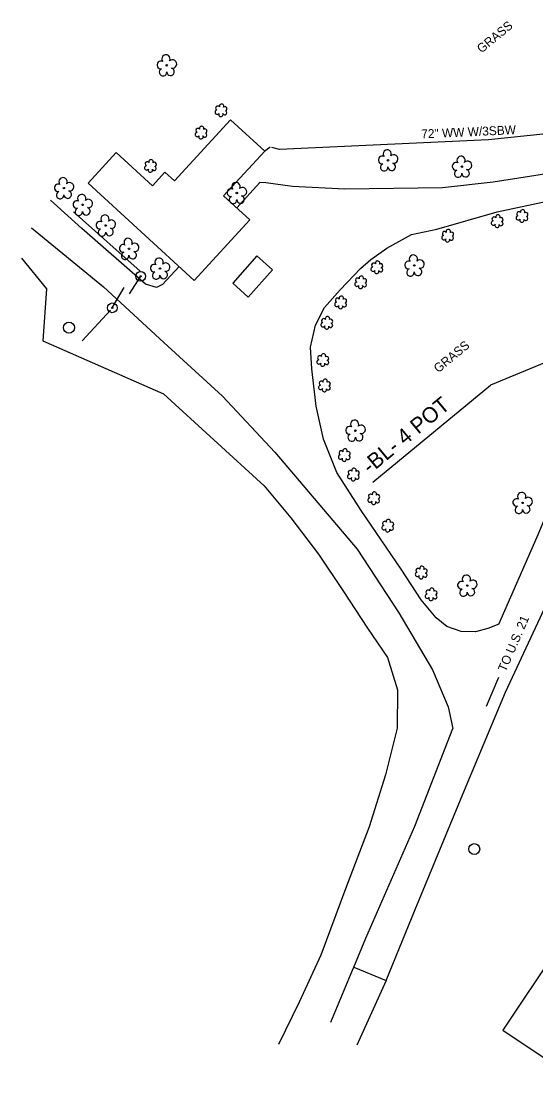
# Model space of a CAD drawing. Extents: x 1435573 to 1437263, y 981340 to 982884.
# Drawn here: x 1435573.4 to 1435804.6, y 981403.5 to 981887.2 of the extents above; entities that cross this region are included whole.
import ezdxf

# ---------------------------------------------------------------- set-up
doc = ezdxf.new("R2010")
doc.units = 0
for name, color, linetype in [('Exist Building', 7, 'Continuous'), ('Exist Horizontal Baseline Alignment Station Label', 7, 'Continuous'), ('Exist Other Culture Fence Line', 7, 'Continuous'), ('Exist Other Culture Fence Line Text', 7, 'Continuous'), ('Exist Other Culture Gate', 7, 'Continuous'), ('Exist Other Culture Located Object CELL', 7, 'Continuous'), ('Exist Roads EOP', 7, 'Continuous'), ('Exist Roads EOP Leader', 7, 'Continuous'), ('Exist Roads EOP Other', 7, 'Continuous'), ('Exist Roads EOP Text', 7, 'Continuous'), ('Exist Roads Soil', 7, 'Continuous'), ('Exist Utilities Other Pole CELL', 7, 'Continuous'), ('Exist Vegetation Shrub CELL', 7, 'Continuous'), ('Exist Vegetation Shrub Text', 7, 'Continuous'), ('Exist Vegetation Tree CELL', 7, 'Continuous'), ('Exist Vegetation Woods Line', 7, 'Continuous')]:
    doc.layers.add(name, color=color, linetype=linetype)

msp = doc.modelspace()

# ---------------------------------------------------------------- linework, layer by layer
at = {"layer": 'Exist Building'}
for points in [[(1435651.11, 981770.64), (1435603.35, 981814.47), (1435615.96, 981828.21), (1435632.3, 981813.22), (1435637.97, 981819.4), (1435642.23, 981815.49), (1435667.44, 981842.95), (1435682.81, 981828.84), (1435664.34, 981808.71), (1435676.12, 981797.89)], [(1435675.43, 981763.21), (1435686.34, 981775.46), (1435679.34, 981781.7), (1435668.42, 981769.45)], [(1435789.87, 981433.37), (1435834.55, 981403.48), (1435858.68, 981439.56), (1435814, 981469.45)]]:
    msp.add_lwpolyline(points, close=True, dxfattribs=at)
at = {"layer": 'Exist Horizontal Baseline Alignment Station Label'}
for p in [(1435840.71, 981747.05), (1435731.5, 981679.86)]:
    msp.add_line(p, (1435784.44, 981723.56), dxfattribs=at)
at = {"layer": 'Exist Other Culture Fence Line'}
for points in [[(1435862.69, 981860.78), (1435847.67, 981849.47), (1435829.17, 981841.77), (1435809.36, 981836.69), (1435783.45, 981833.94), (1435689.44, 981829.6)], [(1435626.78, 981774.79), (1435596.78, 981801.58)], [(1435613.47, 981757.3), (1435600.74, 981743.57)]]:
    msp.add_lwpolyline(points, dxfattribs=at)
at = {"layer": 'Exist Other Culture Gate'}
for points in [[(1435682.79, 981828.77), (1435685.33, 981830.85)], [(1435689.44, 981829.6), (1435686.04, 981830.42)], [(1435627.02, 981772.56), (1435621.93, 981764.67)], [(1435614.28, 981758.35), (1435619.63, 981767.47)]]:
    msp.add_lwpolyline(points, dxfattribs=at)
at = {"layer": 'Exist Other Culture Located Object CELL'}
for centre, radius in [((1435627.02, 981772.56), 2.18), ((1435627.02, 981772.56), 0.24), ((1435614.28, 981758.35), 2.18), ((1435614.28, 981758.35), 0.24)]:
    msp.add_circle(centre, radius, dxfattribs=at)
at = {"layer": 'Exist Roads EOP'}
for points in [[(1435788.13, 981615.94), (1435805.42, 981655.37), (1435822.36, 981695.64)], [(1435722.91, 981461.69), (1435737.42, 981455.72), (1435750.46, 981487.59), (1435772.74, 981541.33), (1435791.09, 981585.49), (1435812.8, 981632), (1435833.87, 981683.58)], [(1435722.91, 981461.69), (1435728.38, 981474.68), (1435750.29, 981525.18), (1435767.45, 981569.1)]]:
    msp.add_lwpolyline(points, dxfattribs=at)
at = {"layer": 'Exist Roads EOP Leader'}
msp.add_lwpolyline([(1435782.6, 981579.19), (1435788.16, 981592.17)], dxfattribs=at)
at = {"layer": 'Exist Roads EOP Other'}
for points in [[(1435894.69, 981862.87), (1435885.86, 981852.99), (1435875.39, 981842.31), (1435869.41, 981837.88), (1435855.42, 981831.03), (1435838.61, 981825.35), (1435818.32, 981819.97), (1435785.65, 981814.88), (1435762.77, 981812.3), (1435718.8, 981811.75), (1435695.28, 981812.98), (1435683.33, 981814.66), (1435680.68, 981814.69), (1435670.22, 981803.31)], [(1435788.13, 981615.94), (1435783.12, 981614.09), (1435777.68, 981612.51), (1435771.11, 981612.7), (1435764.68, 981614.94), (1435759.95, 981618.88), (1435753.2, 981626.99), (1435744.23, 981640.76), (1435726.26, 981667.12), (1435715.26, 981684.29), (1435709.2, 981699.19), (1435705.91, 981714.16), (1435703.97, 981730.92), (1435703.49, 981740.62), (1435705.64, 981750.54), (1435709.7, 981758.46), (1435716.78, 981766.47), (1435725.9, 981775.98), (1435730.55, 981780.15), (1435737.76, 981785.19), (1435748.85, 981791.4), (1435760.17, 981793.8), (1435787.32, 981801.59), (1435821.85, 981808.84)], [(1435644.28, 981776.91), (1435636.84, 981768.81), (1435634.22, 981767.5), (1435629.17, 981769.07), (1435600.57, 981794.11), (1435586.44, 981806.83)], [(1435577.92, 981794.31), (1435610.39, 981767.77), (1435637.41, 981742.74), (1435663.85, 981718.66), (1435687.45, 981693.35), (1435724.46, 981649.72), (1435743.11, 981621.1), (1435758.3, 981595.49), (1435765.27, 981578.82), (1435767.45, 981569.1)]]:
    msp.add_lwpolyline(points, dxfattribs=at)
at = {"layer": 'Exist Roads Soil'}
for points in [[(1435712.51, 981437), (1435722.37, 981460.4)], [(1435722.37, 981460.4), (1435722.91, 981461.69)], [(1435737.42, 981455.72), (1435724.21, 981426.56)]]:
    msp.add_lwpolyline(points, dxfattribs=at)
at = {"layer": 'Exist Utilities Other Pole CELL'}
for centre in [(1435594.79, 981749.44), (1435777.07, 981514.83)]:
    msp.add_circle(centre, 2.46, dxfattribs=at)
at = {"layer": 'Exist Vegetation Shrub CELL'}
for p, q in [((1435663.22, 981847.05), (1435663.22, 981847.05)), ((1435654.26, 981837.02), (1435654.26, 981837.02)), ((1435631.49, 981822.02), (1435631.49, 981822.02)), ((1435798.61, 981799.49), (1435798.61, 981799.49)), ((1435787.48, 981797.17), (1435787.48, 981797.17)), ((1435765.17, 981790.61), (1435765.17, 981790.61)), ((1435733.34, 981776.42), (1435733.34, 981776.42)), ((1435726.07, 981769.66), (1435726.07, 981769.66)), ((1435717.04, 981760.61), (1435717.04, 981760.61)), ((1435710.83, 981751.42), (1435710.83, 981751.42)), ((1435709.04, 981734.7), (1435709.04, 981734.7)), ((1435709.77, 981723.24), (1435709.77, 981723.24)), ((1435718.7, 981691.91), (1435718.7, 981691.91)), ((1435722.78, 981683.14), (1435722.78, 981683.14)), ((1435731.95, 981672.51), (1435731.95, 981672.51)), ((1435738.24, 981660.14), (1435738.24, 981660.14)), ((1435753.31, 981639.06), (1435753.31, 981639.06)), ((1435757.76, 981629.27), (1435757.76, 981629.27))]:
    msp.add_line(p, q, dxfattribs=at)
for centre, radius, start, end in [((1435661.42, 981846.35), 0.955, 95.1099, 327.9534), ((1435661.73, 981848.18), 0.968, 35.8908, 245.4216), ((1435663.45, 981849.1), 0.99, 334.8391, 200.4717), ((1435664.85, 981846.13), 0.937, 204.9913, 73.4601), ((1435664.89, 981847.92), 0.929, 284.4567, 126.0861), ((1435663.09, 981845.37), 0.984, 151.2797, 21.387), ((1435652.46, 981836.32), 0.955, 95.1099, 327.9534), ((1435652.77, 981838.15), 0.968, 35.8908, 245.4216), ((1435654.49, 981839.06), 0.99, 334.8391, 200.4717), ((1435655.89, 981836.09), 0.937, 204.9913, 73.4601), ((1435655.93, 981837.89), 0.929, 284.4567, 126.0861), ((1435654.13, 981835.34), 0.984, 151.2797, 21.387), ((1435629.69, 981821.32), 0.955, 95.1099, 327.9534), ((1435630.01, 981823.15), 0.968, 35.8908, 245.4216), ((1435631.72, 981824.06), 0.99, 334.8391, 200.4717), ((1435633.13, 981821.1), 0.937, 204.9913, 73.4601), ((1435633.17, 981822.89), 0.929, 284.4567, 126.0861), ((1435631.37, 981820.34), 0.984, 151.2797, 21.387), ((1435798.84, 981801.53), 0.99, 334.8391, 200.4717), ((1435786, 981798.3), 0.968, 35.8908, 245.4216), ((1435787.71, 981799.21), 0.99, 334.8391, 200.4717), ((1435789.15, 981798.04), 0.929, 284.4567, 126.0861), ((1435796.81, 981798.79), 0.955, 95.1099, 327.9534), ((1435797.13, 981800.62), 0.968, 35.8908, 245.4216), ((1435798.48, 981797.81), 0.984, 151.2797, 21.387), ((1435800.25, 981798.56), 0.937, 204.9913, 73.4601), ((1435800.28, 981800.36), 0.929, 284.4567, 126.0861), ((1435765.39, 981792.65), 0.99, 334.8391, 200.4717), ((1435785.68, 981796.47), 0.955, 95.1099, 327.9534), ((1435787.35, 981795.49), 0.984, 151.2797, 21.387), ((1435789.12, 981796.24), 0.937, 204.9913, 73.4601), ((1435763.37, 981789.91), 0.955, 95.1099, 327.9534), ((1435763.68, 981791.74), 0.968, 35.8908, 245.4216), ((1435765.04, 981788.93), 0.984, 151.2797, 21.387), ((1435766.8, 981789.68), 0.937, 204.9913, 73.4601), ((1435766.84, 981791.48), 0.929, 284.4567, 126.0861), ((1435731.86, 981777.55), 0.968, 35.8908, 245.4216), ((1435733.57, 981778.47), 0.99, 334.8391, 200.4717), ((1435731.54, 981775.72), 0.955, 95.1099, 327.9534), ((1435733.21, 981774.74), 0.984, 151.2797, 21.387), ((1435734.98, 981775.5), 0.937, 204.9913, 73.4601), ((1435735.01, 981777.29), 0.929, 284.4567, 126.0861), ((1435724.27, 981768.95), 0.955, 95.1099, 327.9534), ((1435724.59, 981770.79), 0.968, 35.8908, 245.4216), ((1435726.3, 981771.7), 0.99, 334.8391, 200.4717), ((1435727.71, 981768.73), 0.937, 204.9913, 73.4601), ((1435727.74, 981770.53), 0.929, 284.4567, 126.0861), ((1435725.94, 981767.98), 0.984, 151.2797, 21.387), ((1435715.24, 981759.91), 0.955, 95.1099, 327.9534), ((1435715.56, 981761.74), 0.968, 35.8908, 245.4216), ((1435716.91, 981758.93), 0.984, 151.2797, 21.387), ((1435717.27, 981762.65), 0.99, 334.8391, 200.4717), ((1435718.68, 981759.68), 0.937, 204.9913, 73.4601), ((1435718.71, 981761.48), 0.929, 284.4567, 126.0861), ((1435711.06, 981753.46), 0.99, 334.8391, 200.4717), ((1435709.03, 981750.72), 0.955, 95.1099, 327.9534), ((1435709.35, 981752.55), 0.968, 35.8908, 245.4216), ((1435710.7, 981749.74), 0.984, 151.2797, 21.387), ((1435712.47, 981750.49), 0.937, 204.9913, 73.4601), ((1435712.5, 981752.29), 0.929, 284.4567, 126.0861), ((1435707.24, 981734), 0.955, 95.1099, 327.9534), ((1435707.56, 981735.83), 0.968, 35.8908, 245.4216), ((1435709.27, 981736.74), 0.99, 334.8391, 200.4717), ((1435710.71, 981735.57), 0.929, 284.4567, 126.0861), ((1435708.91, 981733.02), 0.984, 151.2797, 21.387), ((1435710.68, 981733.77), 0.937, 204.9913, 73.4601), ((1435708.29, 981724.37), 0.968, 35.8908, 245.4216), ((1435710, 981725.29), 0.99, 334.8391, 200.4717), ((1435707.97, 981722.54), 0.955, 95.1099, 327.9534), ((1435709.65, 981721.56), 0.984, 151.2797, 21.387), ((1435711.41, 981722.32), 0.937, 204.9913, 73.4601), ((1435711.45, 981724.11), 0.929, 284.4567, 126.0861), ((1435716.9, 981691.21), 0.955, 95.1099, 327.9534), ((1435717.22, 981693.04), 0.968, 35.8908, 245.4216), ((1435718.93, 981693.95), 0.99, 334.8391, 200.4717), ((1435720.34, 981690.98), 0.937, 204.9913, 73.4601), ((1435720.37, 981692.78), 0.929, 284.4567, 126.0861), ((1435718.57, 981690.23), 0.984, 151.2797, 21.387), ((1435720.98, 981682.43), 0.955, 95.1099, 327.9534), ((1435721.3, 981684.27), 0.968, 35.8908, 245.4216), ((1435722.66, 981681.46), 0.984, 151.2797, 21.387), ((1435723.01, 981685.18), 0.99, 334.8391, 200.4717), ((1435724.42, 981682.21), 0.937, 204.9913, 73.4601), ((1435724.46, 981684.01), 0.929, 284.4567, 126.0861), ((1435730.15, 981671.8), 0.955, 95.1099, 327.9534), ((1435730.46, 981673.63), 0.968, 35.8908, 245.4216), ((1435732.18, 981674.55), 0.99, 334.8391, 200.4717), ((1435733.58, 981671.58), 0.937, 204.9913, 73.4601), ((1435733.62, 981673.37), 0.929, 284.4567, 126.0861), ((1435731.82, 981670.82), 0.984, 151.2797, 21.387), ((1435736.76, 981661.27), 0.968, 35.8908, 245.4216), ((1435738.47, 981662.18), 0.99, 334.8391, 200.4717), ((1435736.44, 981659.43), 0.955, 95.1099, 327.9534), ((1435738.12, 981658.46), 0.984, 151.2797, 21.387), ((1435739.88, 981659.21), 0.937, 204.9913, 73.4601), ((1435739.92, 981661.01), 0.929, 284.4567, 126.0861), ((1435751.51, 981638.35), 0.955, 95.1099, 327.9534), ((1435751.83, 981640.19), 0.968, 35.8908, 245.4216), ((1435753.54, 981641.1), 0.99, 334.8391, 200.4717), ((1435754.95, 981638.13), 0.937, 204.9913, 73.4601), ((1435754.98, 981639.93), 0.929, 284.4567, 126.0861), ((1435753.18, 981637.38), 0.984, 151.2797, 21.387), ((1435755.96, 981628.57), 0.955, 95.1099, 327.9534), ((1435756.28, 981630.4), 0.968, 35.8908, 245.4216), ((1435757.99, 981631.31), 0.99, 334.8391, 200.4717), ((1435759.4, 981628.35), 0.937, 204.9913, 73.4601), ((1435759.43, 981630.14), 0.929, 284.4567, 126.0861), ((1435757.63, 981627.59), 0.984, 151.2797, 21.387)]:
    msp.add_arc(centre, radius, start, end, dxfattribs=at)
at = {"layer": 'Exist Vegetation Tree CELL'}
for p, q in [((1435638.78, 981867.48), (1435638.78, 981867.48)), ((1435738.3, 981824.73), (1435738.3, 981824.73)), ((1435771.52, 981821.87), (1435771.52, 981821.87)), ((1435592.52, 981812.2), (1435592.52, 981812.2)), ((1435670.29, 981810.03), (1435670.29, 981810.03)), ((1435600.93, 981804.69), (1435600.93, 981804.69)), ((1435611.34, 981795.39), (1435611.34, 981795.39)), ((1435621.79, 981784.93), (1435621.79, 981784.93)), ((1435635.71, 981776.04), (1435635.71, 981776.04)), ((1435750.11, 981777.43), (1435750.11, 981777.43)), ((1435723.65, 981703.09), (1435723.65, 981703.09)), ((1435798.8, 981670.6), (1435798.8, 981670.6)), ((1435773.92, 981633.39), (1435773.92, 981633.39))]:
    msp.add_line(p, q, dxfattribs=at)
for centre in [(1435638.78, 981867.48), (1435738.3, 981824.73), (1435771.52, 981821.87), (1435592.52, 981812.2), (1435670.29, 981810.03), (1435600.93, 981804.69), (1435611.34, 981795.39), (1435621.79, 981784.93), (1435635.71, 981776.04), (1435750.11, 981777.43), (1435723.65, 981703.09), (1435798.8, 981670.6), (1435773.92, 981633.39)]:
    msp.add_circle(centre, 0.326, dxfattribs=at)
for centre, radius, start, end in [((1435638.39, 981870.35), 1.86, 330.1651, 219.7134), ((1435636.17, 981867.63), 1.73, 62.6636, 279.3457), ((1435637.07, 981864.35), 1.69, 111.5671, 6.231), ((1435640.45, 981864.58), 1.7, 181.2822, 74.56), ((1435641.33, 981868.06), 1.9, 257.1011, 134.1999), ((1435737.91, 981827.6), 1.86, 330.1651, 219.7134), ((1435740.85, 981825.32), 1.9, 257.1011, 134.1999), ((1435735.69, 981824.88), 1.73, 62.6636, 279.3457), ((1435736.59, 981821.61), 1.69, 111.5671, 6.231), ((1435739.97, 981821.83), 1.7, 181.2822, 74.56), ((1435768.91, 981822.02), 1.73, 62.6636, 279.3457), ((1435771.13, 981824.74), 1.86, 330.1651, 219.7134), ((1435774.07, 981822.46), 1.9, 257.1011, 134.1999), ((1435769.81, 981818.75), 1.69, 111.5671, 6.231), ((1435773.19, 981818.97), 1.7, 181.2822, 74.56), ((1435589.92, 981812.35), 1.73, 62.6636, 279.3457), ((1435592.14, 981815.07), 1.86, 330.1651, 219.7134), ((1435595.07, 981812.79), 1.9, 257.1011, 134.1999), ((1435669.9, 981812.91), 1.86, 330.1651, 219.7134), ((1435672.84, 981810.62), 1.9, 257.1011, 134.1999), ((1435590.82, 981809.08), 1.69, 111.5671, 6.231), ((1435594.2, 981809.3), 1.7, 181.2822, 74.56), ((1435600.55, 981807.56), 1.86, 330.1651, 219.7134), ((1435667.68, 981810.19), 1.73, 62.6636, 279.3457), ((1435668.58, 981806.91), 1.69, 111.5671, 6.231), ((1435671.96, 981807.13), 1.7, 181.2822, 74.56), ((1435598.33, 981804.84), 1.73, 62.6636, 279.3457), ((1435599.23, 981801.57), 1.69, 111.5671, 6.231), ((1435602.61, 981801.79), 1.7, 181.2822, 74.56), ((1435603.48, 981805.28), 1.9, 257.1011, 134.1999), ((1435610.96, 981798.27), 1.86, 330.1651, 219.7134), ((1435613.89, 981795.98), 1.9, 257.1011, 134.1999), ((1435608.73, 981795.55), 1.73, 62.6636, 279.3457), ((1435609.64, 981792.27), 1.69, 111.5671, 6.231), ((1435613.01, 981792.5), 1.7, 181.2822, 74.56), ((1435621.4, 981787.8), 1.86, 330.1651, 219.7134), ((1435619.18, 981785.08), 1.73, 62.6636, 279.3457), ((1435620.08, 981781.81), 1.69, 111.5671, 6.231), ((1435623.46, 981782.03), 1.7, 181.2822, 74.56), ((1435624.34, 981785.52), 1.9, 257.1011, 134.1999), ((1435635.32, 981778.91), 1.86, 330.1651, 219.7134), ((1435638.26, 981776.63), 1.9, 257.1011, 134.1999), ((1435747.5, 981777.59), 1.73, 62.6636, 279.3457), ((1435749.72, 981780.31), 1.86, 330.1651, 219.7134), ((1435752.66, 981778.02), 1.9, 257.1011, 134.1999), ((1435633.1, 981776.19), 1.73, 62.6636, 279.3457), ((1435634, 981772.92), 1.69, 111.5671, 6.231), ((1435637.38, 981773.14), 1.7, 181.2822, 74.56), ((1435748.4, 981774.31), 1.69, 111.5671, 6.231), ((1435751.78, 981774.53), 1.7, 181.2822, 74.56), ((1435723.26, 981705.97), 1.86, 330.1651, 219.7134), ((1435721.04, 981703.25), 1.73, 62.6636, 279.3457), ((1435721.94, 981699.97), 1.69, 111.5671, 6.231), ((1435725.32, 981700.19), 1.7, 181.2822, 74.56), ((1435726.2, 981703.68), 1.9, 257.1011, 134.1999), ((1435796.19, 981670.75), 1.73, 62.6636, 279.3457), ((1435798.41, 981673.47), 1.86, 330.1651, 219.7134), ((1435801.34, 981671.19), 1.9, 257.1011, 134.1999), ((1435797.09, 981667.48), 1.69, 111.5671, 6.231), ((1435800.47, 981667.7), 1.7, 181.2822, 74.56), ((1435773.53, 981636.26), 1.86, 330.1651, 219.7134), ((1435771.31, 981633.54), 1.73, 62.6636, 279.3457), ((1435776.47, 981633.98), 1.9, 257.1011, 134.1999), ((1435772.21, 981630.27), 1.69, 111.5671, 6.231), ((1435775.59, 981630.49), 1.7, 181.2822, 74.56)]:
    msp.add_arc(centre, radius, start, end, dxfattribs=at)
at = {"layer": 'Exist Vegetation Woods Line'}
msp.add_lwpolyline([(1435573.44, 981780.71), (1435584.62, 981766.89), (1435583.09, 981743.45), (1435637.31, 981719.65), (1435682.55, 981678.28), (1435694.56, 981663.81), (1435706.98, 981647.5), (1435717.96, 981631.09), (1435729.11, 981614.23), (1435737.99, 981601.08), (1435742.53, 981586.47), (1435742.41, 981569.26), (1435737.2, 981548.28), (1435729.77, 981524.86), (1435719.23, 981496.91), (1435708.05, 981467.11), (1435698.37, 981445.97), (1435689.08, 981426.91)], dxfattribs=at)

# ---------------------------------------------------------------- texts
at = {"layer": 'Exist Horizontal Baseline Alignment Station Label'}
msp.add_text('-BL- 4 POT  ', height=7, rotation=39.5399, dxfattribs=at).set_placement((1435730.19, 981683.34))
at = {"layer": 'Exist Other Culture Fence Line Text'}
msp.add_text('72" WW W/3SBW', height=4, rotation=2.643, dxfattribs=at).set_placement((1435753.32, 981834.55))
at = {"layer": 'Exist Roads EOP Text'}
msp.add_text('TO U.S. 21', height=4, rotation=66.5508, dxfattribs=at).set_placement((1435791.23, 981594.27))
at = {"layer": 'Exist Vegetation Shrub Text'}
for p in [(1435780.33, 981872.75), (1435760.89, 981728.89)]:
    msp.add_text('GRASS', height=4, rotation=39.5399, dxfattribs=at).set_placement(p)

doc.saveas('drawing.dxf')
